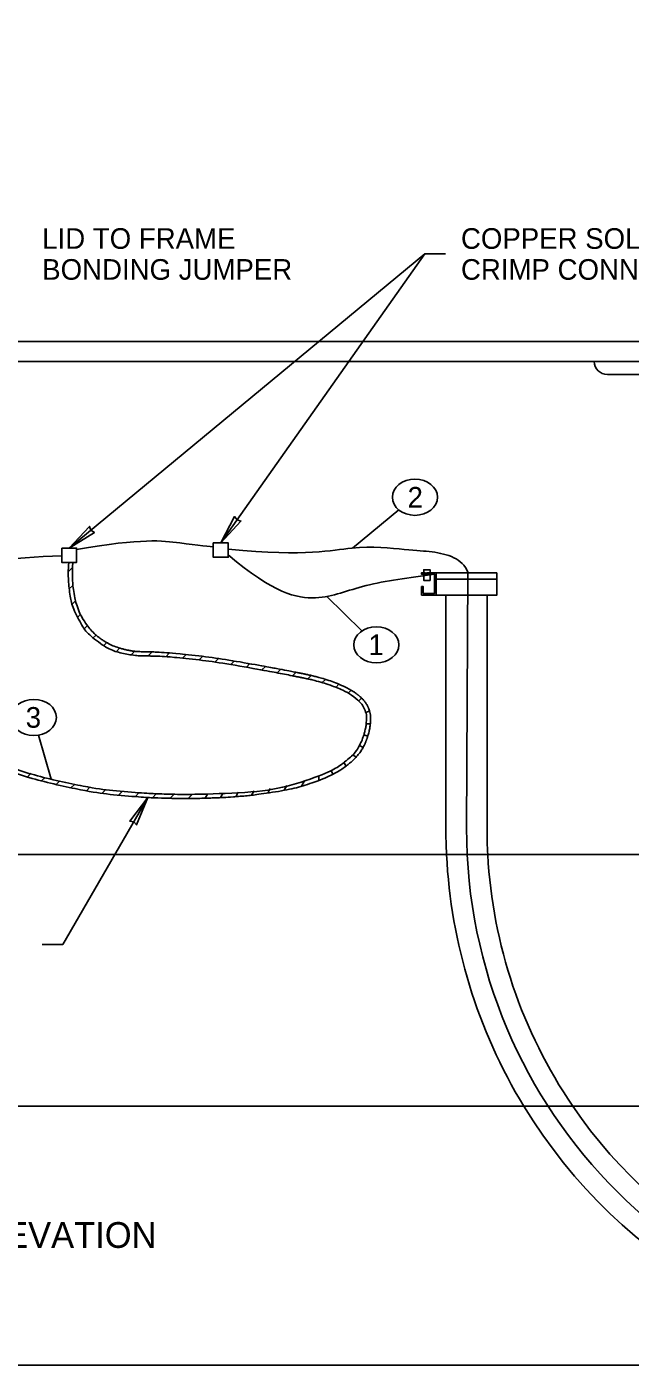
# Model space of a CAD drawing. Extents: x 99862 to 103151, y 100000 to 102076.
# Drawn here: x 101573 to 102040, y 100000 to 101038 of the extents above; entities that cross this region are included whole.
import ezdxf

# ---------------------------------------------------------------- set-up
doc = ezdxf.new("R2010")
doc.units = 0
for name, color, linetype in [('Level 1', 7, 'Continuous'), ('Level 11', 7, 'Continuous'), ('Level 12', 7, 'Continuous'), ('Level 13', 7, 'Continuous'), ('Level 15', 7, 'Continuous'), ('Level 18', 7, 'Continuous'), ('Level 2', 7, 'Continuous'), ('Level 20', 7, 'Continuous'), ('Level 22', 7, 'Continuous'), ('Level 3', 7, 'Continuous')]:
    doc.layers.add(name, color=color, linetype=linetype)

msp = doc.modelspace()

# ---------------------------------------------------------------- linework, layer by layer
at = {"layer": 'Level 1'}
msp.add_lwpolyline([(99862, 99999.5), (103151, 99999.5), (103151, 102075.5), (99862, 102075.5)], close=True, dxfattribs=at)
at = {"layer": 'Level 11'}
msp.add_lwpolyline([(100996.7, 100395.5), (102203.1, 100395.5), (102203.1, 100200.5), (100996.7, 100200.5)], dxfattribs=at)
at = {"layer": 'Level 12'}
msp.add_line((101913.4, 100415.9), (101914.6, 100614.1), dxfattribs=at)
for points in [[(101717.2, 100637.2), (101728.8, 100637.2), (101728.8, 100626.1), (101717.2, 100626.1)], [(101599.7, 100633.2), (101611.3, 100633.2), (101611.3, 100622.1), (101599.7, 100622.1)]]:
    msp.add_lwpolyline(points, close=True, dxfattribs=at)
msp.add_arc((102311.9, 100415.9), 398.4, 180, 270, dxfattribs=at)
for points in [[(101275.9, 100614.1), (101291.1, 100639.7), (101347.2, 100641.8), (101494.5, 100610.7), (101561, 100626.7), (101599.7, 100627.1)], [(101611.3, 100632.1), (101662.7, 100641), (101692.6, 100636.9), (101716.7, 100634.2), (101717.2, 100634.1)], [(101728.8, 100632.4), (101791.4, 100626.5), (101825.8, 100636.7), (101869.7, 100631.3), (101886.5, 100630.9), (101904.9, 100626.7), (101912.3, 100620.2), (101914.8, 100614.1)], [(101888.7, 100612.9), (101869.1, 100610.1), (101831.4, 100605.6), (101800.2, 100590.2), (101763.9, 100598), (101728.8, 100628)]]:
    msp.add_open_spline(points, degree=3, dxfattribs=at)
at = {"layer": 'Level 13'}
for p, q in [((101937, 100609.1), (101889.9, 100609.1)), ((101896.9, 100609.1), (101929.9, 100609.1)), ((101897.5, 100415.9), (101897.5, 100596.7)), ((101929.4, 100415.9), (101929.4, 100596.7))]:
    msp.add_line(p, q, dxfattribs=at)
for points in [[(101882.5, 100614.1), (101889.9, 100614.1), (101889.9, 100596.7), (101878.7, 100596.7), (101878.7, 100603.3), (101879.9, 100603.3), (101879.9, 100598), (101888.7, 100598), (101888.7, 100612.9), (101882.5, 100612.9)], [(101881.6, 100614.1), (101878.7, 100614.1), (101878.7, 100612.9), (101881.6, 100612.9)], [(101937, 100614.1), (101889.9, 100614.1), (101889.9, 100596.7), (101937, 100596.7)]]:
    msp.add_lwpolyline(points, close=True, dxfattribs=at)
for points in [[(101880.4, 100614.1), (101880.4, 100616.4), (101885.2, 100616.4), (101885.2, 100614.1)], [(101885.2, 100612.9), (101885.2, 100608.2), (101880.4, 100608.2), (101880.4, 100612.9)]]:
    msp.add_lwpolyline(points, dxfattribs=at)
for radius, start, end in [(414.4, 180, 182.8213), (382.5, 180, 183.057), (414.4, 182.8216, 211.3198), (382.5, 183.057, 214.2727), (414.4, 211.3198, 270), (382.5, 214.2727, 270)]:
    msp.add_arc((102311.9, 100415.9), radius, start, end, dxfattribs=at)
at = {"layer": 'Level 15'}
for p, q in [((101881.2, 100861.3), (101605.5, 100633.2)), ((101723, 100637.2), (101881.2, 100861.3)), ((101897.2, 100861.3), (101881.2, 100861.3)), ((101861.1, 100662.8), (101825, 100633.2)), ((101832.4, 100569), (101804.9, 100595.8)), ((101581.6, 100488.2), (101591.6, 100454.1)), ((101666.5, 100439.8), (101600.6, 100325.8)), ((101584.6, 100325.8), (101600.6, 100325.8))]:
    msp.add_line(p, q, dxfattribs=at)
for points in [[(101723, 100637.2), (101738.6, 100654.1), (101735.6, 100655), (101733.7, 100657.6)], [(101605.5, 100633.2), (101625, 100645.4), (101622.3, 100647), (101621.2, 100650)], [(101666.5, 100439.8), (101652.5, 100421.5), (101655.6, 100421), (101657.6, 100418.5)]]:
    msp.add_lwpolyline(points, close=True, dxfattribs=at)
at = {"layer": 'Level 18'}
for p, q in [((101604.8, 100614.9), (101608.1, 100618.2)), ((101605.5, 100601.5), (101608.4, 100604.3)), ((101607.9, 100589.7), (101610.5, 100592.3)), ((101611.9, 100579.5), (101614.3, 100581.9)), ((101617.3, 100570.8), (101619.6, 100573.1)), ((101624.1, 100563.5), (101626.4, 100565.7)), ((101632.3, 100557.6), (101634.7, 100559.9)), ((101642.1, 100553.1), (101644.6, 100555.6)), ((101653.5, 100550.4), (101656.3, 100553.2)), ((101666.8, 100549.6), (101669.9, 100552.7)), ((101680.3, 100549), (101683.3, 100551.9)), ((101693.4, 100547.9), (101696.2, 100550.7)), ((101706, 100546.4), (101708.9, 100549.2)), ((101718.5, 100544.7), (101721.3, 100547.5)), ((101730.7, 100542.8), (101733.5, 100545.6)), ((101742.9, 100540.8), (101745.6, 100543.6)), ((101754.9, 100538.7), (101757.6, 100541.4)), ((101766.8, 100536.5), (101769.5, 100539.2)), ((101778.7, 100534.2), (101781.4, 100536.9)), ((101790.4, 100531.8), (101793.1, 100534.4)), ((101801.7, 100528.9), (101804.2, 100531.4)), ((101812.2, 100525.2), (101814.6, 100527.7)), ((101821.7, 100520.6), (101824, 100523)), ((101829.9, 100514.7), (101832.1, 100516.9)), ((101835.3, 100505.7), (101838.3, 100506.8)), ((101835.7, 100496.8), (101838.9, 100496.8)), ((101830.5, 100480.1), (101833.3, 100478.6)), ((101833.9, 100488.3), (101836.9, 100487.4)), ((101825.4, 100473), (101827.9, 100471.1)), ((101573.4, 100456.2), (101576, 100458.7)), ((101808.5, 100460.7), (101809.9, 100457.9)), ((101818.5, 100466.9), (101820.1, 100464.2)), ((101584.2, 100452.9), (101586.8, 100455.4)), ((101595.4, 100449.9), (101598, 100452.5)), ((101606.9, 100447.2), (101609.6, 100449.9)), ((101618.8, 100445), (101621.5, 100447.8)), ((101772.2, 100445.5), (101774.3, 100449.2)), ((101785.6, 100448.7), (101787.9, 100452.6)), ((101798.9, 100456.4), (101798.9, 100453)), ((101631, 100443.1), (101633.9, 100445.9)), ((101643.7, 100441.6), (101646.6, 100444.5)), ((101656.7, 100440.4), (101659.6, 100443.4)), ((101670, 100439.6), (101673, 100442.7)), ((101683.7, 100439.2), (101686.8, 100442.3)), ((101697.7, 100439), (101700.9, 100442.2)), ((101710.9, 100439.2), (101712.7, 100442.4)), ((101722.7, 100439.7), (101724.5, 100442.9)), ((101734.7, 100440.4), (101736.6, 100443.8)), ((101746.9, 100441.6), (101748.8, 100445)), ((101759.4, 100443.2), (101761.4, 100446.8))]:
    msp.add_line(p, q, dxfattribs=at)
for points in [[(101201.3, 100750.3), (101246.1, 100744.8), (101280.7, 100728.6), (101340.9, 100692.3), (101365.8, 100672), (101389, 100643.6), (101393.2, 100637.8), (101397.5, 100631.1), (101398, 100630.3), (101398.9, 100628.8), (101399.2, 100628.3), (101400.4, 100626.5), (101402.7, 100622.8), (101411.2, 100609.4), (101419.6, 100597.3), (101440.9, 100568.5), (101456.7, 100549.6), (101482.6, 100521.8), (101491.6, 100512.6), (101502.2, 100502.4), (101503.4, 100501.2), (101505.7, 100498.9), (101506.7, 100498), (101510, 100495.1), (101512.2, 100493.1), (101519.1, 100487.5), (101524, 100484), (101549.8, 100467.4), (101575.2, 100457.2), (101621.1, 100447.4), (101637.7, 100445.1), (101664.5, 100443), (101673.8, 100442.6), (101692.9, 100442.1), (101703, 100442.2), (101749.3, 100443.5), (101778.1, 100448.5), (101807.4, 100459.6), (101814.8, 100463.9), (101825.7, 100472.7), (101829.1, 100477.1), (101832.1, 100483.2), (101832.6, 100484.5), (101833.3, 100486.5), (101833.6, 100487.3), (101834.1, 100488.9), (101834.3, 100489.7), (101835.3, 100493.4), (101835.7, 100496), (101836.2, 100502.8), (101835.6, 100505.7), (101833.3, 100510.9), (101831.5, 100513.4), (101824.1, 100519.5), (101818.5, 100522.8), (101806.9, 100527.3), (101802.5, 100528.7), (101795.1, 100530.7), (101792.5, 100531.3), (101788.4, 100532.2), (101787.1, 100532.5), (101784, 100533.1), (101782.5, 100533.4), (101768.8, 100536.1), (101757.3, 100538.3), (101725.3, 100543.9), (101707, 100546.5), (101684.4, 100548.8), (101677.7, 100549.2), (101670.4, 100549.5), (101669, 100549.5), (101667, 100549.6), (101666.3, 100549.6), (101665.3, 100549.6), (101665.1, 100549.6), (101664.1, 100549.6), (101663.6, 100549.6), (101659, 100549.7), (101655, 100550), (101643, 100552.3), (101635, 100555.3), (101621.2, 100565.3), (101615.6, 100572.2), (101608.2, 100587), (101606.2, 100595), (101604.7, 100609.2), (101604.7, 100615.5), (101605.1, 100622)], [(101200.9, 100747.1), (101223.9, 100744.3), (101244.2, 100738.6), (101271.7, 100727.7), (101280.3, 100723.7), (101296.7, 100715.2), (101304.5, 100710.6), (101326.9, 100696.8), (101340.3, 100687.2), (101364.2, 100667.1), (101374.6, 100656.5), (101385.7, 100642.6), (101387.8, 100639.8), (101391.8, 100634.1), (101393.7, 100631.2), (101395.6, 100628.1), (101395.7, 100627.9), (101396, 100627.6), (101396.1, 100627.4), (101396.4, 100626.9), (101396.5, 100626.6), (101396.9, 100626), (101397.1, 100625.7), (101397.5, 100625.1), (101397.7, 100624.8), (101398.6, 100623.3), (101399.4, 100622.1), (101401.7, 100618.4), (101409.5, 100606.3), (101417.9, 100594.3), (101439.1, 100565.7), (101454.8, 100547), (101480.6, 100519.3), (101489.5, 100510.2), (101500.1, 100500), (101501.2, 100498.9), (101503.6, 100496.6), (101504.6, 100495.7), (101507.9, 100492.7), (101510.1, 100490.8), (101517.1, 100485.1), (101522, 100481.5), (101548, 100464.7), (101573.4, 100454.5), (101619, 100444.6), (101635.5, 100442.2), (101662, 100440), (101671.2, 100439.5), (101683, 100439.2), (101685.4, 100439.1), (101690.2, 100439.1), (101692.7, 100439), (101699.9, 100439), (101704.8, 100439.1), (101711.8, 100439.2), (101714.1, 100439.3), (101718.6, 100439.5), (101725.3, 100439.8), (101731.8, 100440.2), (101744.2, 100441.2), (101752, 100442.1), (101773.8, 100445.4), (101786.3, 100448.4), (101801.6, 100453.9), (101806.2, 100455.9), (101814.3, 100460.1), (101817.8, 100462.4), (101821.5, 100465.2), (101822.2, 100465.8), (101823.6, 100466.9), (101824.3, 100467.5), (101826.2, 100469.3), (101827.3, 100470.4), (101830.5, 100474), (101832.2, 100476.5), (101833.9, 100479.8), (101834.3, 100480.4), (101834.9, 100481.7), (101835.2, 100482.4), (101835.6, 100483.5), (101835.7, 100483.8), (101836, 100484.5), (101836.1, 100484.9), (101836.4, 100485.6), (101836.5, 100486), (101836.8, 100486.9), (101836.9, 100487.3), (101838, 100491), (101838.6, 100493.9), (101838.9, 100497.1), (101839, 100497.7), (101839.1, 100498.9), (101839.1, 100499.5), (101839.1, 100501.2), (101839.1, 100502.2), (101838.8, 100505.2), (101838.4, 100506.9), (101837.6, 100508.9), (101837.5, 100509.2), (101837.1, 100510), (101837, 100510.4), (101836.4, 100511.5), (101835.9, 100512.3), (101834.3, 100514.6), (101833, 100516.1), (101830.8, 100518.1), (101830.3, 100518.5), (101829.6, 100519.1), (101829.4, 100519.3), (101828.8, 100519.7), (101828.6, 100519.9), (101827.2, 100520.9), (101826, 100521.8), (101821.9, 100524.2), (101818.8, 100525.9), (101811.4, 100529), (101807.3, 100530.5), (101800.2, 100532.6), (101797.8, 100533.3), (101793.9, 100534.2), (101792.6, 100534.5), (101790.6, 100535), (101789.9, 100535.1), (101788.5, 100535.4), (101787.8, 100535.6), (101786.7, 100535.8), (101786.3, 100535.9), (101785.6, 100536), (101784.4, 100536.3), (101783.3, 100536.5), (101781, 100537), (101779.5, 100537.2), (101775, 100538.1), (101766.2, 100539.8), (101757.8, 100541.4), (101730.7, 100546.2), (101712, 100549), (101688.7, 100551.6), (101681.7, 100552.1), (101672.4, 100552.6), (101669.5, 100552.7), (101666.5, 100552.7), (101666.2, 100552.7), (101665.8, 100552.7), (101665.7, 100552.7), (101665.5, 100552.7), (101665.5, 100552.7), (101665.2, 100552.7), (101665.1, 100552.7), (101664.8, 100552.7), (101664.7, 100552.7), (101664.4, 100552.7), (101664.1, 100552.7), (101663.7, 100552.8), (101663, 100552.8), (101662.5, 100552.8), (101660.1, 100552.9), (101658.1, 100553), (101654.3, 100553.4), (101652.4, 100553.7), (101648.7, 100554.5), (101646.8, 100555), (101641.2, 100556.7), (101637.6, 100558.2), (101632.5, 100561.1), (101630.9, 100562.2), (101627.7, 100564.5), (101626.2, 100565.8), (101621.9, 100570), (101619.4, 100573.1), (101615.2, 100579.7), (101613.5, 100583.2), (101610.9, 100590.4), (101609.9, 100594.1), (101608.6, 100601.7), (101608.2, 100605.6), (101607.9, 100613.5), (101608, 100617.6), (101608.3, 100621.7)]]:
    msp.add_open_spline(points, degree=3, dxfattribs=at)
at = {"layer": 'Level 2'}
msp.add_line((102022.7, 100767.8), (102064.6, 100767.8), dxfattribs=at)
msp.add_arc((102022.7, 100778), 10.2, 180.1625, 270, dxfattribs=at)
at = {"layer": 'Level 20'}
for centre in [(101873.5, 100672.6), (101843.6, 100558.2), (101578.1, 100501.9)]:
    msp.add_ellipse(centre, major_axis=(-17.5, 0), ratio=0.8, dxfattribs=at)
at = {"layer": 'Level 22'}
msp.add_line((101929.4, 100596.7), (101897.5, 100596.7), dxfattribs=at)
at = {"layer": 'Level 3'}
for p, q in [((101146, 100793.5), (102050.1, 100793.5)), ((101079.2, 100778), (102059.1, 100778))]:
    msp.add_line(p, q, dxfattribs=at)

# ---------------------------------------------------------------- texts
at = {"layer": 'Level 20'}
for s, p in [('LID TO FRAME', (101584.6, 100865.3)), ('COPPER SOLDERLESS', (101909.2, 100865.3)), ('BONDING JUMPER', (101584.6, 100841.3)), ('CRIMP CONNECTOR', (101909.2, 100841.3))]:
    msp.add_text(s, height=16, rotation=360, dxfattribs=at).set_placement(p)
for s, height, p in [('2', 16, (101867.8, 100664.6)), ('1', 16, (101837.5, 100550.2)), ('3', 16, (101571.8, 100493.9)), ('ELEVATION', 20, (101523.1, 100090.5))]:
    msp.add_text(s, height=height, dxfattribs=at).set_placement(p)

doc.saveas('drawing.dxf')
